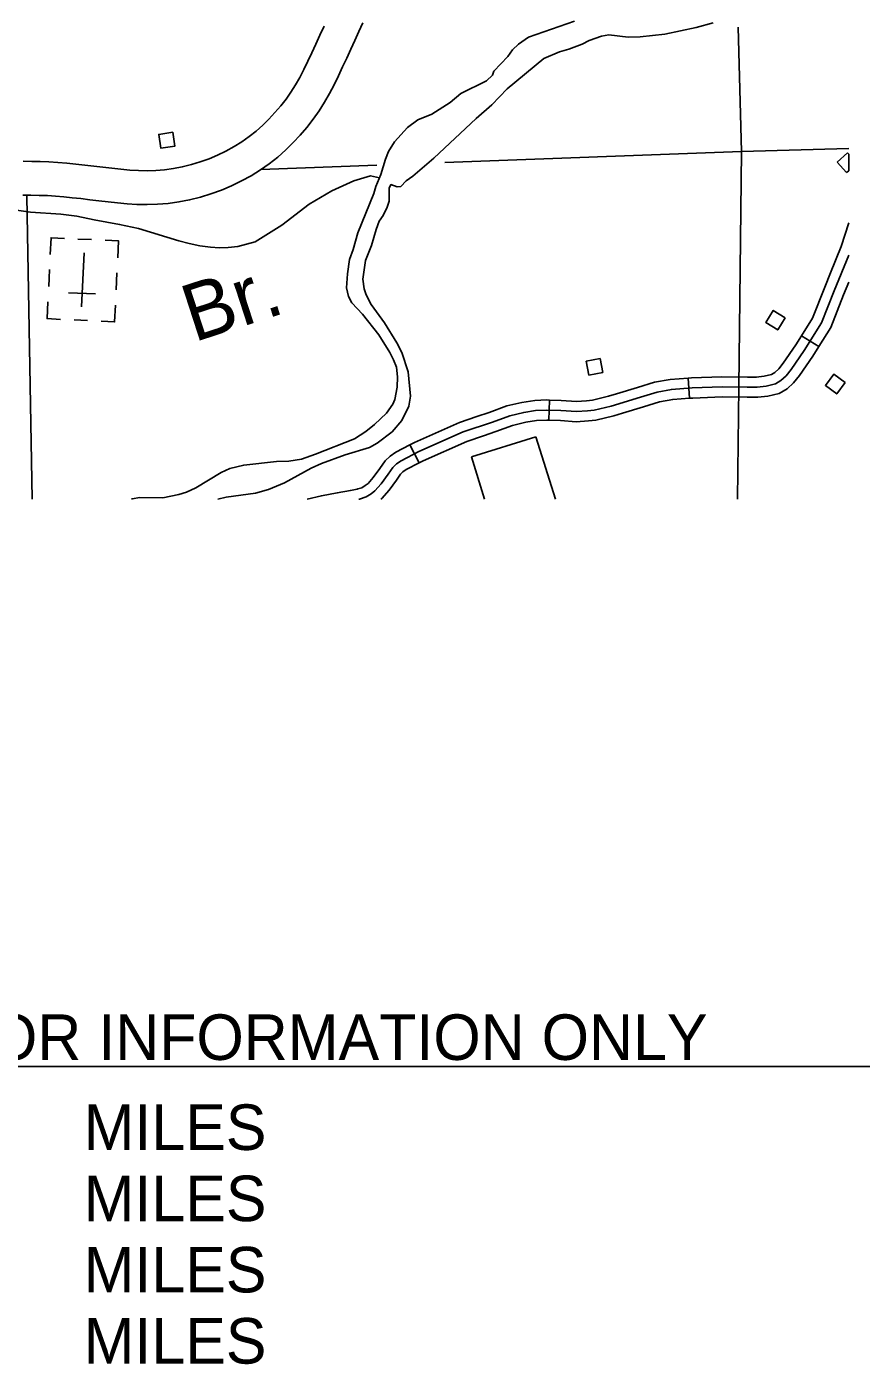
# Model space of a CAD drawing. Extents: x 1370130 to 1380143, y 377636 to 380256.
# Drawn here: x 1378782.2 to 1379041.6, y 377636.3 to 378052.1 of the extents above; entities that cross this region are included whole.
import ezdxf

# ---------------------------------------------------------------- set-up
doc = ezdxf.new("R2010")
doc.units = 0
for name, color, linetype in [('3', 7, 'Continuous'), ('Level 15', 7, 'Continuous'), ('Level 31', 7, 'Continuous'), ('Level 35', 7, 'Continuous'), ('Level 5', 7, 'Continuous'), ('Level 56', 7, 'Continuous'), ('Level 57', 7, 'Continuous'), ('Level 6', 7, 'Continuous')]:
    doc.layers.add(name, color=color, linetype=linetype)

msp = doc.modelspace()

# ---------------------------------------------------------------- linework, layer by layer
at = {"layer": '3'}
msp.add_line((1378019.25, 377728.9), (1379071.72, 377728.9), dxfattribs=at)
at = {"layer": 'Level 15'}
msp.add_line((1378783.7, 378010.21), (1378783.7, 378010.21), dxfattribs=at)
for points in [[(1378783.48, 377999.71), (1378786.06, 377999.65), (1378788.58, 377999.58), (1378791.09, 377999.42), (1378793.65, 377999.2), (1378796.3, 377998.93), (1378799.01, 377998.63), (1378801.77, 377998.3), (1378804.6, 377997.96), (1378807.48, 377997.63), (1378810.39, 377997.33), (1378813.34, 377997.06), (1378816.41, 377996.86), (1378819.58, 377996.79), (1378822.83, 377996.88), (1378826.13, 377997.15), (1378829.47, 377997.61), (1378832.81, 377998.25), (1378836.13, 377999.08), (1378839.42, 378000.09), (1378842.68, 378001.27), (1378845.86, 378002.62), (1378848.94, 378004.12), (1378851.93, 378005.77), (1378854.8, 378007.56), (1378857.56, 378009.49), (1378860.19, 378011.56), (1378862.69, 378013.76), (1378865.02, 378016.07), (1378867.17, 378018.41), (1378869.22, 378020.8), (1378871.18, 378023.3), (1378873.02, 378025.9), (1378874.71, 378028.58), (1378876.27, 378031.31), (1378877.7, 378034.06), (1378879.05, 378036.81), (1378880.35, 378039.57), (1378881.62, 378042.34), (1378882.88, 378045.1), (1378884.13, 378047.83), (1378885.4, 378050.56), (1378886.68, 378053.3)], [(1378874.6, 378052.24), (1378873.32, 378049.46), (1378872.07, 378046.7), (1378870.83, 378044), (1378869.58, 378041.36), (1378868.33, 378038.8), (1378867.05, 378036.34), (1378865.71, 378033.99), (1378864.28, 378031.74), (1378862.76, 378029.57), (1378861.11, 378027.47), (1378859.32, 378025.39), (1378857.45, 378023.35), (1378855.52, 378021.43), (1378853.47, 378019.63), (1378851.3, 378017.93), (1378849, 378016.32), (1378846.61, 378014.82), (1378844.1, 378013.44), (1378841.5, 378012.18), (1378838.84, 378011.04), (1378836.11, 378010.05), (1378833.33, 378009.21), (1378830.53, 378008.51), (1378827.75, 378007.97), (1378824.99, 378007.59), (1378822.26, 378007.36), (1378819.56, 378007.29), (1378816.87, 378007.35), (1378814.16, 378007.53), (1378811.4, 378007.78), (1378808.62, 378008.07), (1378805.83, 378008.39), (1378803.02, 378008.73), (1378800.21, 378009.06), (1378797.42, 378009.37), (1378794.64, 378009.66), (1378791.87, 378009.89), (1378789.06, 378010.07), (1378786.32, 378010.15), (1378783.7, 378010.21)], [(1378783.7, 378010.21), (1378781.1, 378010.26)], [(1378780.95, 377999.76), (1378783.48, 377999.71)]]:
    msp.add_lwpolyline(points, dxfattribs=at)
at = {"layer": 'Level 31'}
for p, q in [((1379023.01, 377956.02), (1379028.35, 377952.68)), ((1378988.18, 377936.58), (1378987.73, 377942.87)), ((1379010.5, 377937.01), (1379010.5, 377937.01)), ((1378944.44, 377929.73), (1378944.61, 377936.03)), ((1378922.06, 377930.88), (1378922.06, 377930.88)), ((1378901.21, 377922.09), (1378904.12, 377916.51))]:
    msp.add_line(p, q, dxfattribs=at)
for points in [[(1379032.04, 377975.59), (1379035.36, 377983.78), (1379037.67, 377991.14)], [(1378885.37, 377905.22), (1378885.61, 377905.27), (1378887.67, 377905.93), (1378889.18, 377906.9), (1378890.39, 377907.81), (1378892.33, 377909.99), (1378894.51, 377912.96), (1378895.96, 377915.07), (1378897.11, 377916.16), (1378898.51, 377917.13), (1378904.03, 377920.01), (1378917.82, 377926.11), (1378926.91, 377929.21), (1378932.31, 377931.17), (1378936.68, 377932.21), (1378940.36, 377932.78), (1378943.81, 377932.9), (1378948.18, 377932.78), (1378953.01, 377932.44), (1378956.46, 377932.67), (1378958.53, 377932.9), (1378963.82, 377934.16), (1378972.9, 377936.92), (1378978.08, 377938.53), (1378982.56, 377939.34), (1378989, 377939.8), (1378998.31, 377940.14), (1379006.13, 377940.03), (1379009.24, 377940.03), (1379012, 377940.37), (1379014.87, 377941.06), (1379016.6, 377942.1), (1379018.21, 377943.6), (1379019.82, 377945.55), (1379023.84, 377951.42), (1379029.25, 377960.05), (1379033.15, 377969.94), (1379037.67, 377981.08)], [(1379023.01, 377956.02), (1379026.42, 377961.47), (1379030.23, 377971.11), (1379032.04, 377975.59)], [(1379028.35, 377952.68), (1379032.07, 377958.62), (1379036.08, 377968.77), (1379037.67, 377972.69)], [(1379009.72, 377943.26), (1379011.43, 377943.48), (1379013.67, 377944.01), (1379014.69, 377944.63), (1379015.91, 377945.76), (1379017.3, 377947.45), (1379021.21, 377953.15), (1379023.01, 377956.02)], [(1379028.35, 377952.68), (1379026.48, 377949.69), (1379022.34, 377943.66), (1379020.5, 377941.43), (1379018.5, 377939.57), (1379016.08, 377938.11), (1379012.56, 377937.27), (1379010.5, 377937.01)], [(1378965.48, 377937.96), (1378971.98, 377939.93), (1378977.33, 377941.6), (1378982.17, 377942.47), (1378987.73, 377942.87)], [(1378987.73, 377942.87), (1378988.83, 377942.94), (1378998.28, 377943.29), (1379006.16, 377943.18), (1379009.04, 377943.18), (1379009.72, 377943.26)], [(1378944.61, 377936.03), (1378948.33, 377935.93), (1378953.02, 377935.59), (1378956.18, 377935.8), (1378957.99, 377936), (1378962.99, 377937.2), (1378965.48, 377937.96)], [(1378967.32, 377931.93), (1378973.83, 377933.91), (1378978.83, 377935.47), (1378982.95, 377936.21), (1378988.18, 377936.58)], [(1379010.5, 377937.01), (1379009.43, 377936.88), (1379006.11, 377936.88), (1378998.35, 377936.99), (1378989.17, 377936.65), (1378988.18, 377936.58)], [(1378944.61, 377936.03), (1378943.8, 377936.05), (1378940.06, 377935.92), (1378936.07, 377935.3), (1378931.41, 377934.19), (1378925.86, 377932.19), (1378922.06, 377930.88)], [(1378922.06, 377930.88), (1378916.68, 377929.04), (1378902.66, 377922.85), (1378901.21, 377922.09)], [(1378924.1, 377924.92), (1378927.95, 377926.24), (1378933.21, 377928.15), (1378937.29, 377929.11), (1378940.66, 377929.64), (1378943.82, 377929.74), (1378944.44, 377929.73)], [(1378944.44, 377929.73), (1378948.03, 377929.63), (1378953, 377929.28), (1378956.74, 377929.53), (1378959.07, 377929.79), (1378964.64, 377931.12), (1378967.32, 377931.93)], [(1378904.12, 377916.51), (1378905.39, 377917.17), (1378918.97, 377923.17), (1378924.1, 377924.92)], [(1378885.05, 377908.4), (1378886.31, 377908.8), (1378887.38, 377909.49), (1378888.25, 377910.14), (1378889.88, 377911.97), (1378891.94, 377914.78), (1378893.55, 377917.13), (1378895.12, 377918.62), (1378896.88, 377919.84), (1378901.21, 377922.09)], [(1378892.19, 377905.22), (1378892.54, 377905.48), (1378894.78, 377908.01), (1378897.08, 377911.13), (1378898.37, 377913.02), (1378899.1, 377913.71), (1378900.14, 377914.43), (1378904.12, 377916.51)], [(1378869.3, 377905.22), (1378873.77, 377906.29), (1378878.69, 377907.15), (1378882.78, 377907.94), (1378884.83, 377908.32), (1378885.05, 377908.4)]]:
    msp.add_lwpolyline(points, dxfattribs=at)
at = {"layer": 'Level 35'}
for points in [[(1378995.52, 378053.27), (1378990.28, 378051.86), (1378980.47, 378049.72), (1378972.85, 378048.92), (1378969.1, 378048.85), (1378963.15, 378049.52), (1378960.8, 378049.13), (1378957.03, 378047.79), (1378954.78, 378046.61), (1378950.72, 378045.05), (1378947.79, 378044.23), (1378942.9, 378042.23), (1378931.55, 378032.74), (1378926.72, 378027.84), (1378921.87, 378023.57), (1378908.72, 378011.21), (1378902.18, 378005.6), (1378900.1, 378004.13), (1378898.45, 378002.45), (1378897.36, 378002.3), (1378895.36, 378002.98), (1378894.84, 378001.87), (1378894.79, 377997.83), (1378894.2, 377996.01), (1378892.95, 377993.41), (1378891.72, 377991.62), (1378890.76, 377989.07), (1378889.34, 377984.12), (1378887.5, 377979.45), (1378886.61, 377973.62)], [(1378952.44, 378053.84), (1378938.09, 378048.78), (1378935.06, 378046.7), (1378933.16, 378044.85), (1378931.72, 378042.84), (1378927.39, 378038.21), (1378926.91, 378037.06), (1378925.05, 378035.25), (1378917.12, 378031.3), (1378913.77, 378028.53), (1378908.07, 378024.92), (1378903.76, 378023.15), (1378900.52, 378020.8), (1378896.53, 378016.34), (1378894.61, 378013.27)], [(1378894.61, 378013.27), (1378893.64, 378010.94), (1378892.26, 378006.19), (1378890.66, 378002.41), (1378890.03, 378000.21), (1378885.13, 377988.03), (1378883.68, 377982.78), (1378882.52, 377979.72), (1378881.9, 377975.25), (1378881.6, 377970.91), (1378882.16, 377968.27), (1378883.22, 377966.27), (1378886.53, 377962.68), (1378891.59, 377956.34), (1378895.03, 377950.86), (1378896.22, 377948.57), (1378897.07, 377946.27), (1378897.38, 377943.2), (1378897.28, 377940.04), (1378896.56, 377936.16), (1378895.95, 377934.76), (1378893.99, 377931.98), (1378890.31, 377928.45), (1378887.53, 377926.29), (1378884.04, 377923.94), (1378871.95, 377919.22), (1378867.56, 377917.7), (1378863.61, 377917.03), (1378859.78, 377916.91), (1378849.6, 377915.81), (1378845.28, 377914.75), (1378842.57, 377913.52), (1378834.7, 377908.72), (1378831.78, 377907.4), (1378829.43, 377906.67), (1378824.44, 377905.68), (1378817.36, 377905.7), (1378814.92, 377905.32), (1378814.73, 377905.22)], [(1378861.49, 377990.38), (1378869.94, 377996.87), (1378876.99, 378001.07), (1378883.88, 378004.21), (1378888.99, 378005.7), (1378891.82, 378005.09)], [(1378709.72, 377994.98), (1378719.77, 377994.75), (1378728.62, 377994.94), (1378754.38, 377996.15), (1378760.96, 377996.12), (1378770.37, 377995.61), (1378775.42, 377995.59), (1378783.35, 377994.39), (1378792.75, 377993.81), (1378797.69, 377993.16), (1378803.17, 377992.06), (1378811.04, 377990.6), (1378816.89, 377989.34), (1378829.4, 377985.52), (1378832.62, 377984.71), (1378835.96, 377983.98), (1378839.26, 377983.58), (1378842.13, 377983.35), (1378844.82, 377983.4), (1378847.81, 377983.76), (1378853.13, 377985.26), (1378861.49, 377990.38)], [(1378886.61, 377973.62), (1378887.05, 377970.6), (1378887.63, 377968.72), (1378889.25, 377965.76), (1378893.37, 377960.04), (1378897.17, 377953.81), (1378898.78, 377950.85), (1378900.76, 377944.79), (1378901.42, 377937.19), (1378900.98, 377934.1), (1378898.71, 377929.64), (1378895.71, 377926.16), (1378891.1, 377922.62), (1378888.73, 377921.26), (1378881.1, 377919.04), (1378873.82, 377916.36), (1378870.61, 377914.82), (1378862.27, 377910.27), (1378857.3, 377908.23), (1378853.32, 377907.05), (1378844.16, 377905.8), (1378841.61, 377905.22)]]:
    msp.add_lwpolyline(points, dxfattribs=at)
at = {"layer": 'Level 5'}
for points in [[(1379003.34, 378051.93), (1379004.33, 378013.3)], [(1378912.11, 378009.82), (1379004.33, 378013.3)], [(1379004.33, 378013.3), (1379003.54, 377940.05), (1379003.15, 377905.22)], [(1379004.33, 378013.3), (1379037.67, 378014.23)], [(1378854.95, 378007.66), (1378890.98, 378009.02)]]:
    msp.add_lwpolyline(points, dxfattribs=at)
at = {"layer": 'Level 56'}
for p, q in [((1379034.06, 378009.95), (1379037.28, 378012.9)), ((1379037.28, 378012.9), (1379037.67, 378012.48)), ((1379037.67, 378012.48), (1379037.67, 378007.31)), ((1379037.02, 378006.71), (1379034.06, 378009.95)), ((1379037.67, 378007.31), (1379037.02, 378006.71))]:
    msp.add_line(p, q, dxfattribs=at)
for points in [[(1378827.55, 378019.27), (1378828.21, 378014.95), (1378823.88, 378014.28), (1378823.21, 378018.6)], [(1379017.92, 377961.55), (1379015.6, 377957.84), (1379011.88, 377960.16), (1379014.2, 377963.87)], [(1378960.4, 377948.9), (1378961.23, 377944.6), (1378956.92, 377943.78), (1378956.1, 377948.07)], [(1379036.55, 377941.45), (1379033.94, 377937.94), (1379030.42, 377940.56), (1379033.03, 377944.07)]]:
    msp.add_lwpolyline(points, close=True, dxfattribs=at)
at = {"layer": 'Level 57'}
for p, q in [((1378802.28, 377985.89), (1378798.09, 377986.09)), ((1378799.19, 377965.01), (1378800.01, 377981.79)), ((1378789.11, 377973.91), (1378788.99, 377971.33)), ((1378789.11, 377973.91), (1378789.24, 377976.57)), ((1378809.96, 377970.31), (1378810.22, 377975.55)), ((1378799.6, 377973.4), (1378799.6, 377973.4)), ((1378799.6, 377973.4), (1378799.6, 377973.4)), ((1378803.59, 377969), (1378795.16, 377969.41)), ((1378796.87, 377960.92), (1378801.06, 377960.72)), ((1378920.37, 377918.39), (1378940.41, 377924.64)), ((1378946.48, 377905.22), (1378940.41, 377924.64)), ((1378924.48, 377905.22), (1378920.37, 377918.39))]:
    msp.add_line(p, q, dxfattribs=at)
for points in [[(1378789.47, 377981.25), (1378789.72, 377986.5), (1378793.92, 377986.29)], [(1378806.5, 377985.68), (1378810.7, 377985.48), (1378810.44, 377980.23)], [(1378792.69, 377961.12), (1378788.5, 377961.33), (1378788.75, 377966.57)], [(1378805.28, 377960.51), (1378809.47, 377960.31), (1378809.73, 377965.55)]]:
    msp.add_lwpolyline(points, dxfattribs=at)
at = {"layer": 'Level 6'}
msp.add_lwpolyline([(1378782.23, 377999.39), (1378783.81, 377905.22)], dxfattribs=at)

# ---------------------------------------------------------------- texts
at = {"layer": '3'}
for s, p in [('LENGTH OF PROJECT CALCULATED ALONG C.L. CONSTRUCTION & IS SHOWN FOR INFORMATION ONLY', (1378033.12, 377730.92)), ('MILES', (1378799.85, 377702.94)), ('MILES', (1378799.85, 377680.81)), ('MILES', (1378799.85, 377658.67)), ('MILES', (1378799.85, 377636.54))]:
    msp.add_text(s, height=14.162, dxfattribs=at).set_placement(p)
at = {"layer": 'Level 35'}
msp.add_text('Br.', height=17.741, rotation=17.9866, dxfattribs=at).set_placement((1378834.12, 377953.93))

doc.saveas('drawing.dxf')
